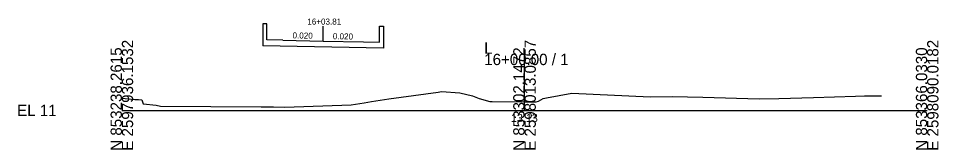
# Model space of a CAD drawing. Extents: x -26 to 1203, y -10 to 9526.
# Drawn here: x -25.7 to 202.8, y 5990.3 to 6022.8 of the extents above; entities that cross this region are included whole.
import ezdxf

# ---------------------------------------------------------------- set-up
doc = ezdxf.new("R2010")
doc.units = 0
for name, color, linetype in [('Exist Cross Section Cell', 7, 'Continuous'), ('Exist XS Center Line Elevation Label', 7, 'Continuous'), ('Exist XS Ground Line', 7, 'Continuous'), ('Prop XS Bridge', 7, 'Continuous'), ('Prop XS SE Text', 7, 'Continuous'), ('Prop XS Side Slope Text', 7, 'Continuous'), ('Prop XS Station Labels', 7, 'Continuous')]:
    doc.layers.add(name, color=color, linetype=linetype)

msp = doc.modelspace()

# ---------------------------------------------------------------- linework, layer by layer
at = {"layer": 'Exist Cross Section Cell'}
for p, q in [((100, 6000), (100, 6014.03)), ((0, 6000), (100, 6000)), ((100, 6000), (200, 6000))]:
    msp.add_line(p, q, dxfattribs=at)
at = {"layer": 'Exist XS Ground Line'}
for p, q in [((66.33, 6002.86), (78.52, 6004.55)), ((78.52, 6004.55), (79.36, 6004.68)), ((79.36, 6004.68), (83.95, 6004.32)), ((83.95, 6004.32), (87.07, 6003.61)), ((87.07, 6003.61), (88.76, 6002.98)), ((105.49, 6003.13), (111.77, 6004.24)), ((111.77, 6004.24), (131.17, 6003.38)), ((182.22, 6003.52), (184.41, 6003.63)), ((184.41, 6003.63), (188.62, 6003.6)), ((0, 6003), (3.19, 6002.67)), ((3.19, 6002.67), (4.13, 6002.68)), ((4.13, 6002.68), (4.96, 6002.63)), ((4.96, 6002.63), (5.31, 6001.6)), ((5.31, 6001.6), (8.56, 6001.28)), ((8.56, 6001.28), (9.61, 6001.08)), ((40.44, 6000.81), (56.94, 6001.42)), ((56.94, 6001.42), (60.17, 6001.85)), ((60.17, 6001.85), (62.04, 6002.18)), ((62.04, 6002.18), (66.33, 6002.86)), ((88.76, 6002.98), (91.36, 6002.23)), ((91.36, 6002.23), (91.97, 6002.19)), ((91.97, 6002.19), (100, 6002.13)), ((100, 6002.13), (102.86, 6002.11)), ((102.86, 6002.11), (103.48, 6002.31)), ((103.48, 6002.31), (104.63, 6002.95)), ((104.63, 6002.95), (105.49, 6003.13)), ((131.17, 6003.38), (136.65, 6003.44)), ((136.65, 6003.44), (144.27, 6003.31)), ((144.27, 6003.31), (158.31, 6002.9)), ((158.31, 6002.9), (163.15, 6002.99)), ((163.15, 6002.99), (171.79, 6003.19)), ((171.79, 6003.19), (182.22, 6003.52)), ((9.61, 6001.08), (34.56, 6000.86)), ((34.56, 6000.86), (37.66, 6000.91)), ((37.66, 6000.91), (40.44, 6000.81))]:
    msp.add_line(p, q, dxfattribs=at)
at = {"layer": 'Prop XS Bridge'}
for p, q in [((35, 6021.46), (35, 6017.46)), ((36, 6021.46), (35, 6021.46)), ((36, 6017.46), (36, 6021.46)), ((64, 6016.9), (64, 6020.9)), ((64, 6020.9), (65, 6020.9)), ((65, 6020.9), (65, 6016.9)), ((35, 6017.46), (35, 6015.96)), ((40, 6017.38), (36, 6017.46)), ((40, 6017.38), (50, 6017.18)), ((65, 6015.4), (35, 6015.96)), ((50, 6017.18), (60, 6016.98)), ((60, 6016.98), (64, 6016.9)), ((65, 6016.9), (65, 6015.4))]:
    msp.add_line(p, q, dxfattribs=at)
at = {"layer": 'Prop XS Side Slope Text'}
msp.add_line((50, 6017.18), (50, 6020.84), dxfattribs=at)

# ---------------------------------------------------------------- texts
at = {"layer": 'Exist Cross Section Cell'}
for s, p in [('E 2597936.1532', (2.8, 5990)), ('E 2598013.0857', (102.8, 5990)), ('E 2598090.0182', (202.8, 5990)), ('N 853238.2615', (0, 5990)), ('N 853302.1472', (100, 5990)), ('N 853366.0330', (200, 5990))]:
    msp.add_text(s, height=2.8, rotation=90, dxfattribs=at).set_placement(p)
for s, p in [('L', (90, 6014.03)), ('16+00.00 / 1', (90, 6011.23)), ('EL 11', (-26, 5998.6))]:
    msp.add_text(s, height=2.8, dxfattribs=at).set_placement(p)
at = {"layer": 'Exist XS Center Line Elevation Label'}
msp.add_text('13.13', height=2, dxfattribs=at).set_placement((96.62, 5997.13))
at = {"layer": 'Prop XS SE Text'}
for p in [(42.38, 6017.84), (52.38, 6017.64)]:
    msp.add_text('0.020', height=1.5, rotation=358.8542, dxfattribs=at).set_placement(p)
at = {"layer": 'Prop XS Station Labels'}
msp.add_text('16+03.81', height=1.5, dxfattribs=at).set_placement((46.06, 6021.25))

doc.saveas('drawing.dxf')
